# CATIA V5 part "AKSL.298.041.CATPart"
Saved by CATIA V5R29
Part number: АКСЛ.298.041
Definition: Уголок 500 мм
Publications: "Грань по длине шипа", "Грань по ширине шипа"
Material "Steel": density 7860 kg/m3, Young's modulus 2e+11 Pa, Poisson ratio 0.266, thermal expansion 1.17e-05 1/K
Bounding box of the stored display mesh (mm): x -250 to 250, y -52 to 51, z -52 to 51
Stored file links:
  Z:\ООО Аксель\Соединения бруса\Соединения бруса\Соединения из листа\АКСЛ.298.040 (Кватро)\AKSL.298.041.CATPart
  Z:\ООО Аксель\Соединения бруса\Соединения бруса\Соединения из листа\АКСЛ.298.040 (Кватро)\AKSL.298.040.CATProduct
  Z:\ООО Аксель\Соединения бруса\Соединения бруса\Соединения из листа\АКСЛ.298.020 (Дуо)\AKSL.298.020.Skelet.CATPart
  Z:\#Catalog_GosNIIAS\Holes&Pockets\Part\Соединение шип-паз\Ship-Paz.CATPart
  Z:\ООО Аксель\Соединения бруса\Соединения бруса\Соединения из листа\АКСЛ.298.040 (Кватро)\AKSL.298.042.CATPart
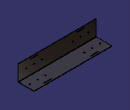
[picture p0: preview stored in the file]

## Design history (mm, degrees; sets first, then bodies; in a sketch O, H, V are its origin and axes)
External parameters (linked from other documents)
  `External.S металла` = 2 mm
  `External.R гиба` = 1.9 mm
  `External.K factor` = 0.49
SheetMetalParameters1: Thickness 2 {= `External.S металла`}, BendRadius 1.9 {= `External.R гиба`}, KFactor 0.49 {= `External.K factor`}, ReliefRadialLength 1, ReliefAxialLength 2, MinimumBendRadius 0
Set1 "Шип в центре грани"
  Extract1 "Плоскость шипа": ExtractElem face of Wall1
  Extract2 "Грань по длине шипа": ExtractElem edge of Extract1
  Extract3 "Грань по ширине шипа": ExtractElem edge of Extract1
Set2
  DatumSurface1: linked copy from another document
  DatumCurve1 to DatumCurve4: linked copy from another document
Body1 (main body)
  ThickSurface1: BotOffset 0, Surface DatumSurface1, TopOffset 2 {= `External.S металла`}
  Recognize1: Recognize_BendTable SheetMetalParameters1, Recognize_ReferenceFace face of ThickSurface1, Recognize_BendDefaultRadius 1.9 {= `External.R гиба`}, KFacteur 0.49 {= SheetMetalParameters1.KFactor}
  d_Bend1: Bend_BendTable SheetMetalParameters1, Bend_Thickness 2 {= `External.S металла`}, Bend_KFactor 0.49 {= SheetMetalParameters1.KFactor}, Bend_FirstSupport face of Recognize1, Bend_SecondSupport face of Recognize1, Bend_KFactorRadius 1.9 {= d_Bend1.CylindricalBendSurf_Radius}, Bend_Deduction -3.2761 {= (d_Bend1.CylindricalBendSurf_Radius+SheetMetalParameters1.Thickness*d_Bend1.Bend_KFactor)*(PI-abs(d_Bend1.BendSurf_OpenAngle))-2*(d_Bend1.CylindricalBendSurf_Radius+SheetMetalParameters1.Thickness)*tan(min((PI-abs(d_Bend1.BendSurf_OpenAngle)),(PI/2))/2)}
  Sketch1 on face of Recognize1, origin (204.5417, -3.091, -52), H (1, 0, 0), V (0, -1, 0)
    point P1 (20.4583, -2.091)
    reference projected line E1 (45.4583, -53.091) -> (45.4583, 45.009) from edge [face of Recognize1 | face of Recognize1]
    reference projected line E2 (45.4583, 48.909) -> (-454.5417, 48.909) from face of Recognize1
    reference projected line E3 (-454.5417, -53.091) -> (45.4583, -53.091) from edge [face of Recognize1 | face of Recognize1]
    distance P1 E1 = 25
    equidistance: E2 E3 P1
  Hole1: placed by Sketch1, at (225, -1, -52) direction (0, 0, 1), diameter 8, through (limit type 6)
  RectPattern1: of Hole1, direction 1 instances 6, spacing 20, along edge [face of Recognize1 | face of Recognize1] reversed
  CutOut1: Direction Sketch3, EndLimit through (limit type 2), Orientation true, Profile Sketch3, StartLimit through (limit type 2)
  SHM_Mirror1: MirroringPlane yz-plane, ObjectToMirror CutOut1
  Sketch2 on face of Recognize1, origin (-214.7754, -52, -5.9745), H (1, 0, 0), V (0, 0, 1)
    point P1 (14.7754, 5.9745)
    reference projected line E1 (-35.2246, -46.0255) -> (464.7754, -46.0255) from face of Recognize1
    reference projected line E2 (-35.2246, 57.9745) -> (464.7754, 57.9745) from edge [face of Recognize1 | face of Recognize1]
    reference projected line E3 (-35.2246, 57.9745) -> (-35.2246, -42.1255) from edge [face of Recognize1 | face of Recognize1]
    distance P1 E3 = 50
    equidistance: E2 E1 P1
  Hole2: placed by Sketch2, at (-200, -52, 0) direction (0, 1, 0), diameter 8, through (limit type 6)
  RectPattern2: of Hole2, direction 1 instances 6, spacing 50, along edge [face of Recognize1 | face of Recognize1]
  Wall1: Thickness 2 {= `External.S металла`}, Profile Sketch4, ListTangentTo face of Recognize1, OffsetValue 0
  Sketch3 on DatumCurve1, origin (-173.9612, -50, 40), H (1, 0, 0), V (0, 0, 1)
    reference projected line E1 (0, -3) -> (0, 0) from DatumCurve2
    reference projected line E2 (0, 0) -> (50, 0) from DatumCurve1
    construction line L1 (0, -1.5) -> (25, -1.5)
    point P5 (0, -1.5)
    point P6 (25, -1.5)
    axis line L2 (25, 0) -> (25, 7.3468)
    point P7 (25, 0)
    line L3 (50.1, -3.1) -> (50.1, 0.1)
    line L4 (50.1, 0.1) -> (-0.1, 0.1)
    line L5 (-0.1, 0.1) -> (-0.1, -3.1)
    line L6 (-0.1, -3.1) -> (50.1, -3.1)
    distance L5 E1 = 0.1
    distance E2 L4 = 0.1
    midpoint: P5 E1, P7 E2
    coincidence: L2 P6
    equidistance: L3 L5 P6, L4 L6 P6
    parallelism: L1 E2, L2 E1, L6 L4, L3 L5
  Sketch4 on face of Recognize1, origin (-52, 0, -52), H (0, -1, 0), V (-1, 0, 0)
    reference projected line E1 (-50, -302) -> (-50, 198) from edge [face of Recognize1 | face of Recognize1]
    line L1 (-51, 188) -> (-50, 188)
    line L2 (-50, 188) -> (-50, -292)
    line L3 (-50, -292) -> (-51, -292)
    line L4 (-51, -292) -> (-51, 188)
    axis line L5 (-50, -52) -> (-51, -52)
    point P7 (-50, -52)
    point P8 (-51, -52)
    distance L2 L4 = 1 {= `External.S металла` /2}
    distance L1 L3 = 480
    length E1 = 500 (reference)
    perpendicularity: L2 L1
    midpoint: P7 L2, P8 L4, P7 E1
    coincidence: L2 E1
  Sketch5 on face of Recognize1, origin (0, -52, 0), H (1, 0, 0), V (0, 0, 1)
    line L1 (-250, 52) -> (-250, 51)
    line L2 (-250, 51) -> (-240.5, 51)
    line L3 (-240.5, 51) -> (-240.5, 50)
    line L4 (-240.5, 50) -> (240.5, 50)
    line L5 (240.5, 50) -> (240.5, 51)
    line L6 (240.5, 51) -> (250, 51)
    line L7 (250, 51) -> (250, 52)
    line L8 (250, 52) -> (-250, 52)
    distance L2 L8 = 1 {= `External.S металла` /2}
    distance L4 L8 = 2 {= `External.S металла`}
    distance L1 L3 = 9.5
    distance L6 L8 = 1 {= `External.S металла` /2}
    distance L5 L7 = 9.5
    vertical: L1 V, L3 V, L5 V, L7 V
    horizontal: L2 H, L4 H, L6 H, L8 H
  CutOut2: Direction Sketch5, EndLimit through (limit type 2), Orientation true, Profile Sketch5, StartLimit through (limit type 2), Thickness1 2, Thickness2 2
  CutOut3: Direction Sketch6, EndLimit through (limit type 2), Orientation true, Profile Sketch6, StartLimit through (limit type 2)
  SHM_Mirror2: MirroringPlane yz-plane, ObjectToMirror CutOut3
  Sketch6 on DatumCurve3, origin (123.9612, 37, -50), H (-1, 0, 0), V (0, 1, 0)
    reference projected line E1 (0, 0) -> (0, 3) from DatumCurve4
    reference projected line E2 (-50, 0) -> (0, 0) from DatumCurve3
    construction line L1 (0, 1.5) -> (-25, 1.5)
    point P5 (0, 1.5)
    point P6 (-25, 1.5)
    axis line L2 (-25, 0) -> (-25, 7.3468)
    point P7 (-25, 0)
    line L3 (-50.1, 3.1) -> (-50.1, -0.1)
    line L4 (-50.1, -0.1) -> (0.1, -0.1)
    line L5 (0.1, -0.1) -> (0.1, 3.1)
    line L6 (0.1, 3.1) -> (-50.1, 3.1)
    distance L5 E1 = 0.1
    distance E2 L4 = 0.1
    midpoint: P5 E1, P7 E2
    coincidence: L2 P6
    equidistance: L3 L5 P6, L4 L6 P6
    parallelism: L1 E2, L2 E1, L6 L4, L3 L5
